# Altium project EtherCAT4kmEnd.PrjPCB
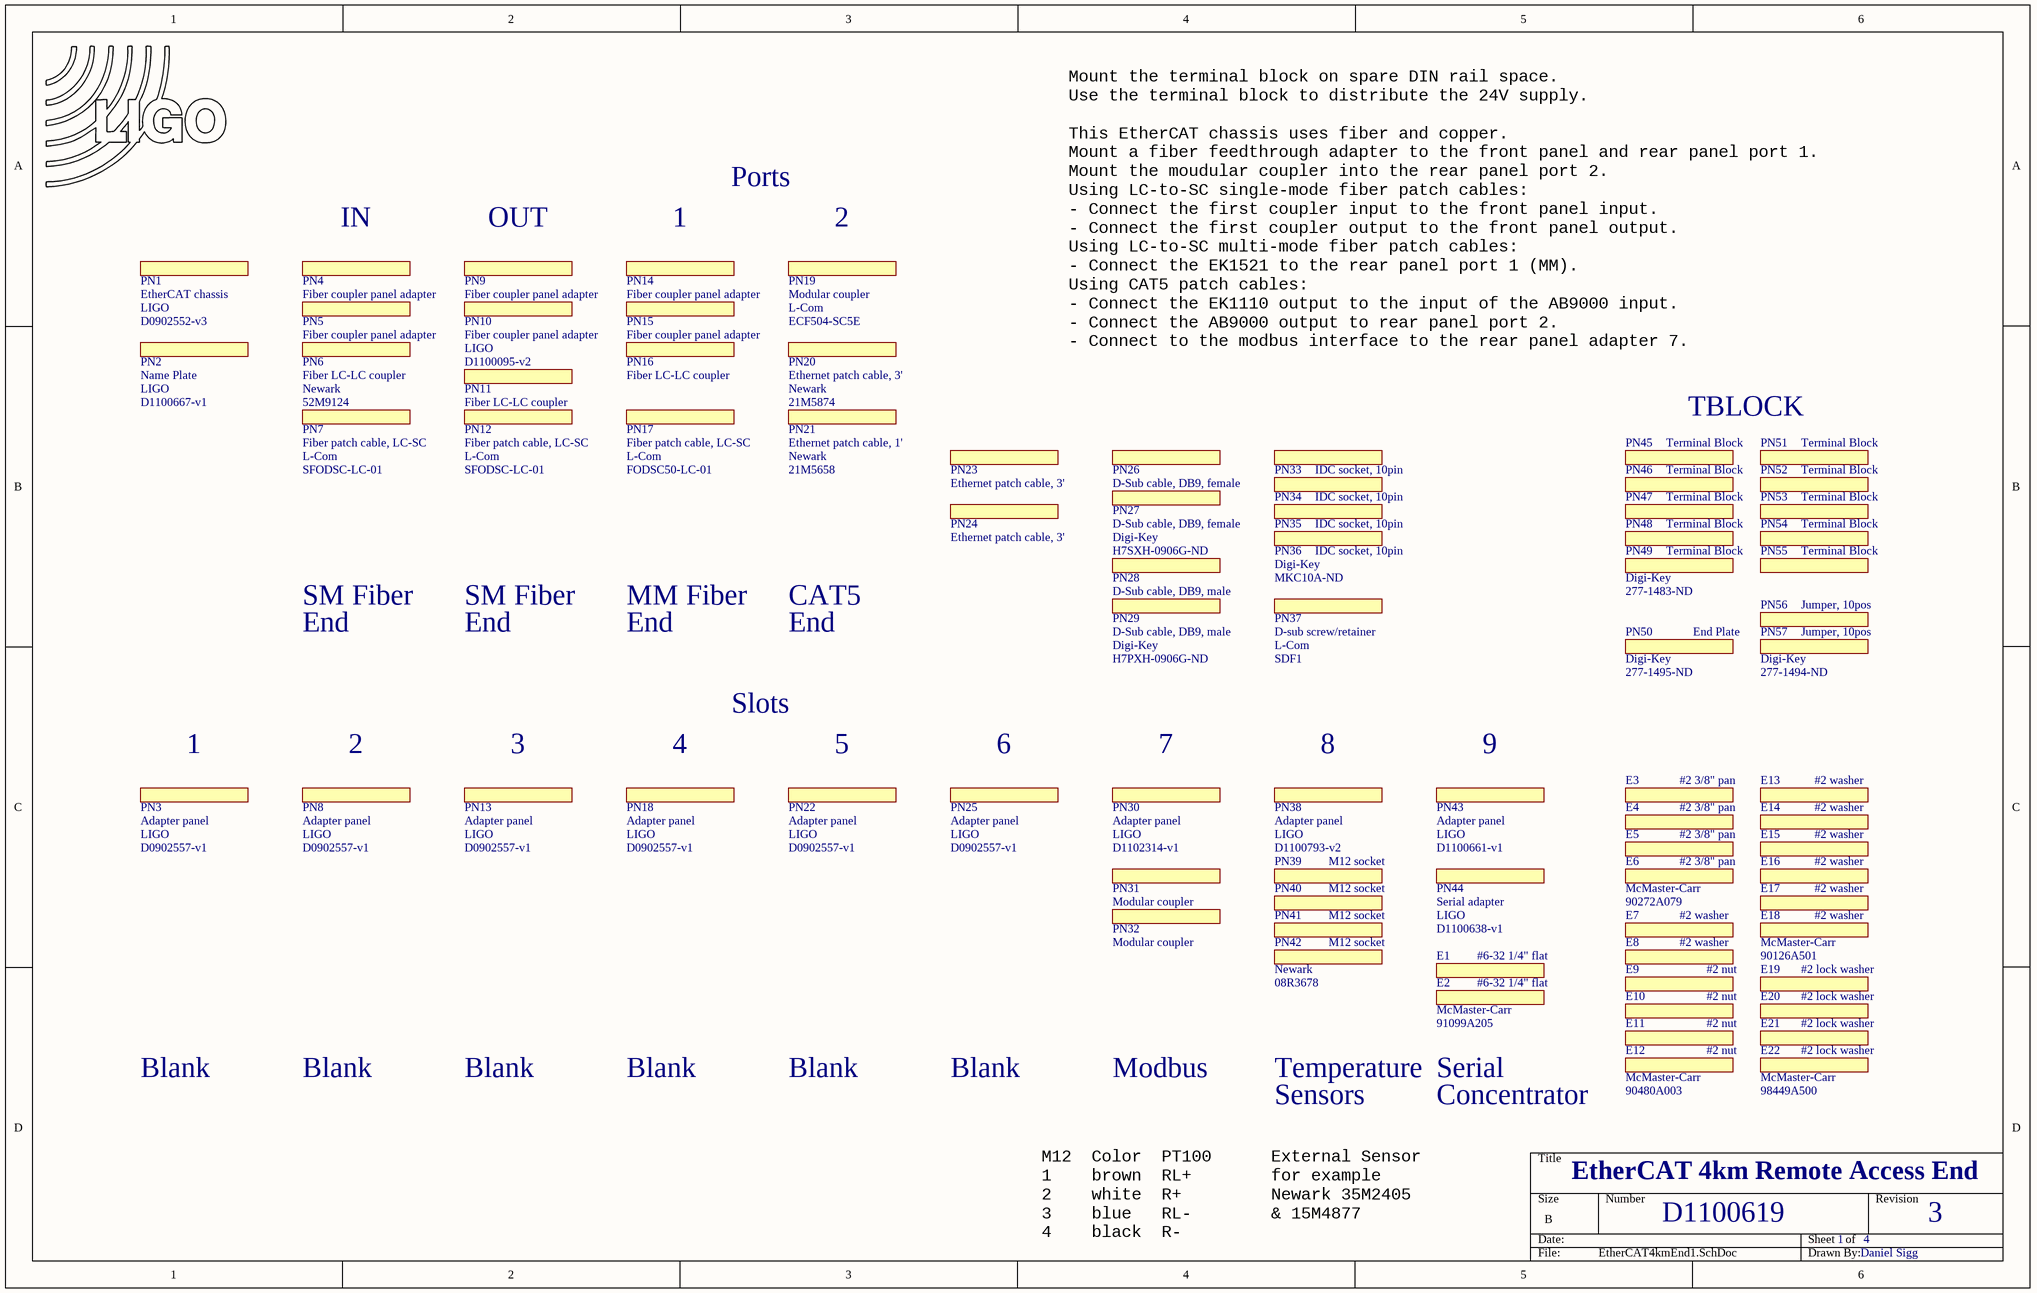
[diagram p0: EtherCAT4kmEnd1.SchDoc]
4 sheets, 87 parts. Net scope: global (net labels, ports and power ports of the same name join across sheets).
Sheets:
  EtherCAT4kmEnd1.SchDoc
  EtherCAT4kmEnd2.SchDoc
  EtherCAT4kmEnd3.SchDoc
  EtherCAT4kmEnd4.SchDoc

## Sheet EtherCAT4kmEnd1.SchDoc: D1100619
size B; Engineer: Daniel Sigg; Revision: 3; PageSetup: Record=PageOptions¦CenterHorizontal=True¦CenterVertical=True¦PrintScale=1.12¦XCorrection=1.00¦YCorrection=1.00¦PrintKind=0¦BorderSize=5000000¦LeftOffset=0¦BottomOffset=0¦Orientation=2¦PaperLength=1000¦PaperWidth=1000¦Scale=100¦PaperSource=7¦PrintQuality=-4¦MediaType=1¦DitherType=10¦PaperKind=11 x 17¦PrintScaleMode=1

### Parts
E1  #6-32 1/4" flat  (mechanical)
E2  #6-32 1/4" flat  Part Number: 91099A205  Distributor: McMaster-Carr  (mechanical)
E3  #2 3/8" pan  (mechanical)
E4  #2 3/8" pan  (mechanical)
E5  #2 3/8" pan  (mechanical)
E6  #2 3/8" pan  Part Number: 90272A079  Distributor: McMaster-Carr  (mechanical)
E7  #2 washer  (mechanical)
E8  #2 washer  (mechanical)
E9  #2 nut  (mechanical)
E10  #2 nut  (mechanical)
E11  #2 nut  (mechanical)
E12  #2 nut  Part Number: 90480A003  Distributor: McMaster-Carr  (mechanical)
E13  #2 washer  (mechanical)
E14  #2 washer  (mechanical)
E15  #2 washer  (mechanical)
E16  #2 washer  (mechanical)
E17  #2 washer  (mechanical)
E18  #2 washer  Part Number: 90126A501  Distributor: McMaster-Carr  (mechanical)
E19  #2 lock washer  (mechanical)
E20  #2 lock washer  (mechanical)
E21  #2 lock washer  (mechanical)
E22  #2 lock washer  Part Number: 98449A500  Distributor: McMaster-Carr  (mechanical)
LOGO?  LIGO logo  [LIGO_LOGO]  (value not drawn)  (graphical)
PN1  EtherCAT chassis  Part Number: D0902552-v3  Distributor: LIGO  (mechanical)
PN2  Name Plate  Part Number: D1100667-v1  Distributor: LIGO  (mechanical)
PN3  Adapter panel  Part Number: D0902557-v1  Distributor: LIGO  (mechanical)
PN4  Fiber coupler panel adapter  (mechanical)
PN5  Fiber coupler panel adapter  (mechanical)
PN6  Fiber LC-LC coupler  Part Number: 52M9124  Distributor: Newark  (mechanical)
PN7  Fiber patch cable, LC-SC  Part Number: SFODSC-LC-01  Distributor: L-Com  (mechanical)
PN8  Adapter panel  Part Number: D0902557-v1  Distributor: LIGO  (mechanical)
PN9  Fiber coupler panel adapter  (mechanical)
PN10  Fiber coupler panel adapter  Part Number: D1100095-v2  Distributor: LIGO  (mechanical)
PN11  Fiber LC-LC coupler  (mechanical)
PN12  Fiber patch cable, LC-SC  Part Number: SFODSC-LC-01  Distributor: L-Com  (mechanical)
PN13  Adapter panel  Part Number: D0902557-v1  Distributor: LIGO  (mechanical)
PN14  Fiber coupler panel adapter  (mechanical)
PN15  Fiber coupler panel adapter  (mechanical)
PN16  Fiber LC-LC coupler  (mechanical)
PN17  Fiber patch cable, LC-SC  Part Number: FODSC50-LC-01  Distributor: L-Com  (mechanical)
PN18  Adapter panel  Part Number: D0902557-v1  Distributor: LIGO  (mechanical)
PN19  Modular coupler  Part Number: ECF504-SC5E  Distributor: L-Com  (mechanical)
PN20  Ethernet patch cable, 3'  Part Number: 21M5874  Distributor: Newark  (mechanical)
PN21  Ethernet patch cable, 1'  Part Number: 21M5658  Distributor: Newark  (mechanical)
PN22  Adapter panel  Part Number: D0902557-v1  Distributor: LIGO  (mechanical)
PN23  Ethernet patch cable, 3'  (mechanical)
PN24  Ethernet patch cable, 3'  (mechanical)
PN25  Adapter panel  Part Number: D0902557-v1  Distributor: LIGO  (mechanical)
PN26  D-Sub cable, DB9, female  (mechanical)
PN27  D-Sub cable, DB9, female  Part Number: H7SXH-0906G-ND  Distributor: Digi-Key  (mechanical)
PN28  D-Sub cable, DB9, male  (mechanical)
PN29  D-Sub cable, DB9, male  Part Number: H7PXH-0906G-ND  Distributor: Digi-Key  (mechanical)
PN30  Adapter panel  Part Number: D1102314-v1  Distributor: LIGO  (mechanical)
PN31  Modular coupler  (mechanical)
PN32  Modular coupler  (mechanical)
PN33  IDC socket, 10pin  (mechanical)
PN34  IDC socket, 10pin  (mechanical)
PN35  IDC socket, 10pin  (mechanical)
PN36  IDC socket, 10pin  Part Number: MKC10A-ND  Distributor: Digi-Key  (mechanical)
PN37  D-sub screw/retainer  Part Number: SDF1  Distributor: L-Com  (mechanical)
PN38  Adapter panel  Part Number: D1100793-v2  Distributor: LIGO  (mechanical)
PN39  M12 socket  (mechanical)
PN40  M12 socket  (mechanical)
PN41  M12 socket  (mechanical)
PN42  M12 socket  Part Number: 08R3678  Distributor: Newark  (mechanical)
PN43  Adapter panel  Part Number: D1100661-v1  Distributor: LIGO  (mechanical)
PN44  Serial adapter  Part Number: D1100638-v1  Distributor: LIGO  (mechanical)
PN45  Terminal Block  (mechanical)
PN46  Terminal Block  (mechanical)
PN47  Terminal Block  (mechanical)
PN48  Terminal Block  (mechanical)
PN49  Terminal Block  Part Number: 277-1483-ND  Distributor: Digi-Key  (mechanical)
PN50  End Plate  Part Number: 277-1495-ND  Distributor: Digi-Key  (mechanical)
PN51  Terminal Block  (mechanical)
PN52  Terminal Block  (mechanical)
PN53  Terminal Block  (mechanical)
PN54  Terminal Block  (mechanical)
PN55  Terminal Block  (mechanical)
PN56  Jumper, 10pos  (mechanical)
PN57  Jumper, 10pos  Part Number: 277-1494-ND  Distributor: Digi-Key  (mechanical)

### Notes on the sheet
- (near PN4) IN
- (near PN9) OUT
- 1
- Ports
- (near PN19) 2
- Mount the terminal block on spare DIN rail space.
  Use the terminal block to distribute the 24V supply.
  This EtherCAT chassis uses fiber and copper.
  Mount a fiber feedthrough adapter to the front panel and rear panel port 1.
  Mount the moudular coupler into the rear panel port 2.
  Using LC-to-SC single-mode fiber patch cables:
  - Connect the first coupler input to the front panel input.
  - Connect the first coupler output to the front panel output.
  Using LC-to-SC multi-mode fiber patch cables:
  - Connect the EK1521 to the rear panel port 1 (MM).
  Using CAT5 patch cables:
  - Connect the EK1110 output to the input of the AB9000 input.
  - Connect the AB9000 output to rear panel port 2.
  - Connect to the modbus interface to the rear panel adapter 7.
- (near PN51) TBLOCK
- SM Fiber
- End
- MM Fiber
- CAT5
- (near PN3) 1
- (near PN8) 2
- (near PN13) 3
- (near PN18) 4
- Slots
- (near PN22) 5
- (near PN25) 6
- (near PN30) 7
- (near PN38) 8
- (near PN43) 9
- Blank
- Modbus
- Temperature
- Sensors
- Serial
- (near E12) Concentrator
- EtherCAT 4km Remote Access End
- M12  Color  PT100
  1    brown  RL+
  2    white  R+
  3    blue   RL-
  4    black  R-
- External Sensor
  for example
  Newark 35M2405
  & 15M4877
- D1100619
- 4
- 3
- Daniel Sigg

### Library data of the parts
E1 = Partlist: #6-32 1/4" flat head screw; Part Number: 91099A205
E2 E6 E12 E18 E22 = Partlist: #6-32 1/4" flat head screw
E3-E5 = Partlist: #6-32 1/4" flat head screw; Part Number: 90272A079
E7 E8 E13-E17 = Partlist: #6-32 1/4" flat head screw; Part Number: 90126A501
E9-E11 = Partlist: #6-32 1/4" flat head screw; Part Number: 90480A003
E19-E21 = Partlist: #6-32 1/4" flat head screw; Part Number: 98449A500
LOGO? = LIGO_logo
PN1 PN2 PN6 PN7 PN10 PN12 PN17 PN19-PN21 PN42 PN44 = Partlist: Additional part number
PN3 PN8 PN13 PN18 PN22 PN25 PN38 = Partlist: Blank
PN4 PN5 PN9 PN14 PN15 = Partlist: Additional part number; Part Number: D1100095-v2
PN11 PN16 = Partlist: Additional part number; Part Number: 52M9124
PN23 PN24 = Partlist: Additional part number; Part Number: 21M5874
PN26 = Partlist: D-Sub cable, DB9, male/open, flat ribbon; Part Number: H7SXH-0906G-ND
PN27 PN29 = Partlist: D-Sub cable, DB9, male/open, flat ribbon
PN28 = Partlist: D-Sub cable, DB9, male/open, flat ribbon; Part Number: H7PXH-0906G-ND
PN30 = Partlist: Modbus adapter, dual
PN31 PN32 = Partlist: Additional part number; Part Number: ECF504-SC5E
PN33-PN35 = Partlist: Part Number: MKC10A-ND
PN36 PN49 PN50 PN57 = Partlist
PN37 = Partlist: D-Sub Hardware Screws and Retainers, Chromate, Pkg/50
PN39-PN41 = Partlist: Additional part number; Part Number: 08R3678
PN43 = Partlist: Serial concentrator
PN45-PN48 PN51-PN55 = Partlist: Part Number: 277-1483-ND
PN56 = Partlist: Part Number: 277-1494-ND

## Sheet EtherCAT4kmEnd2.SchDoc
size B
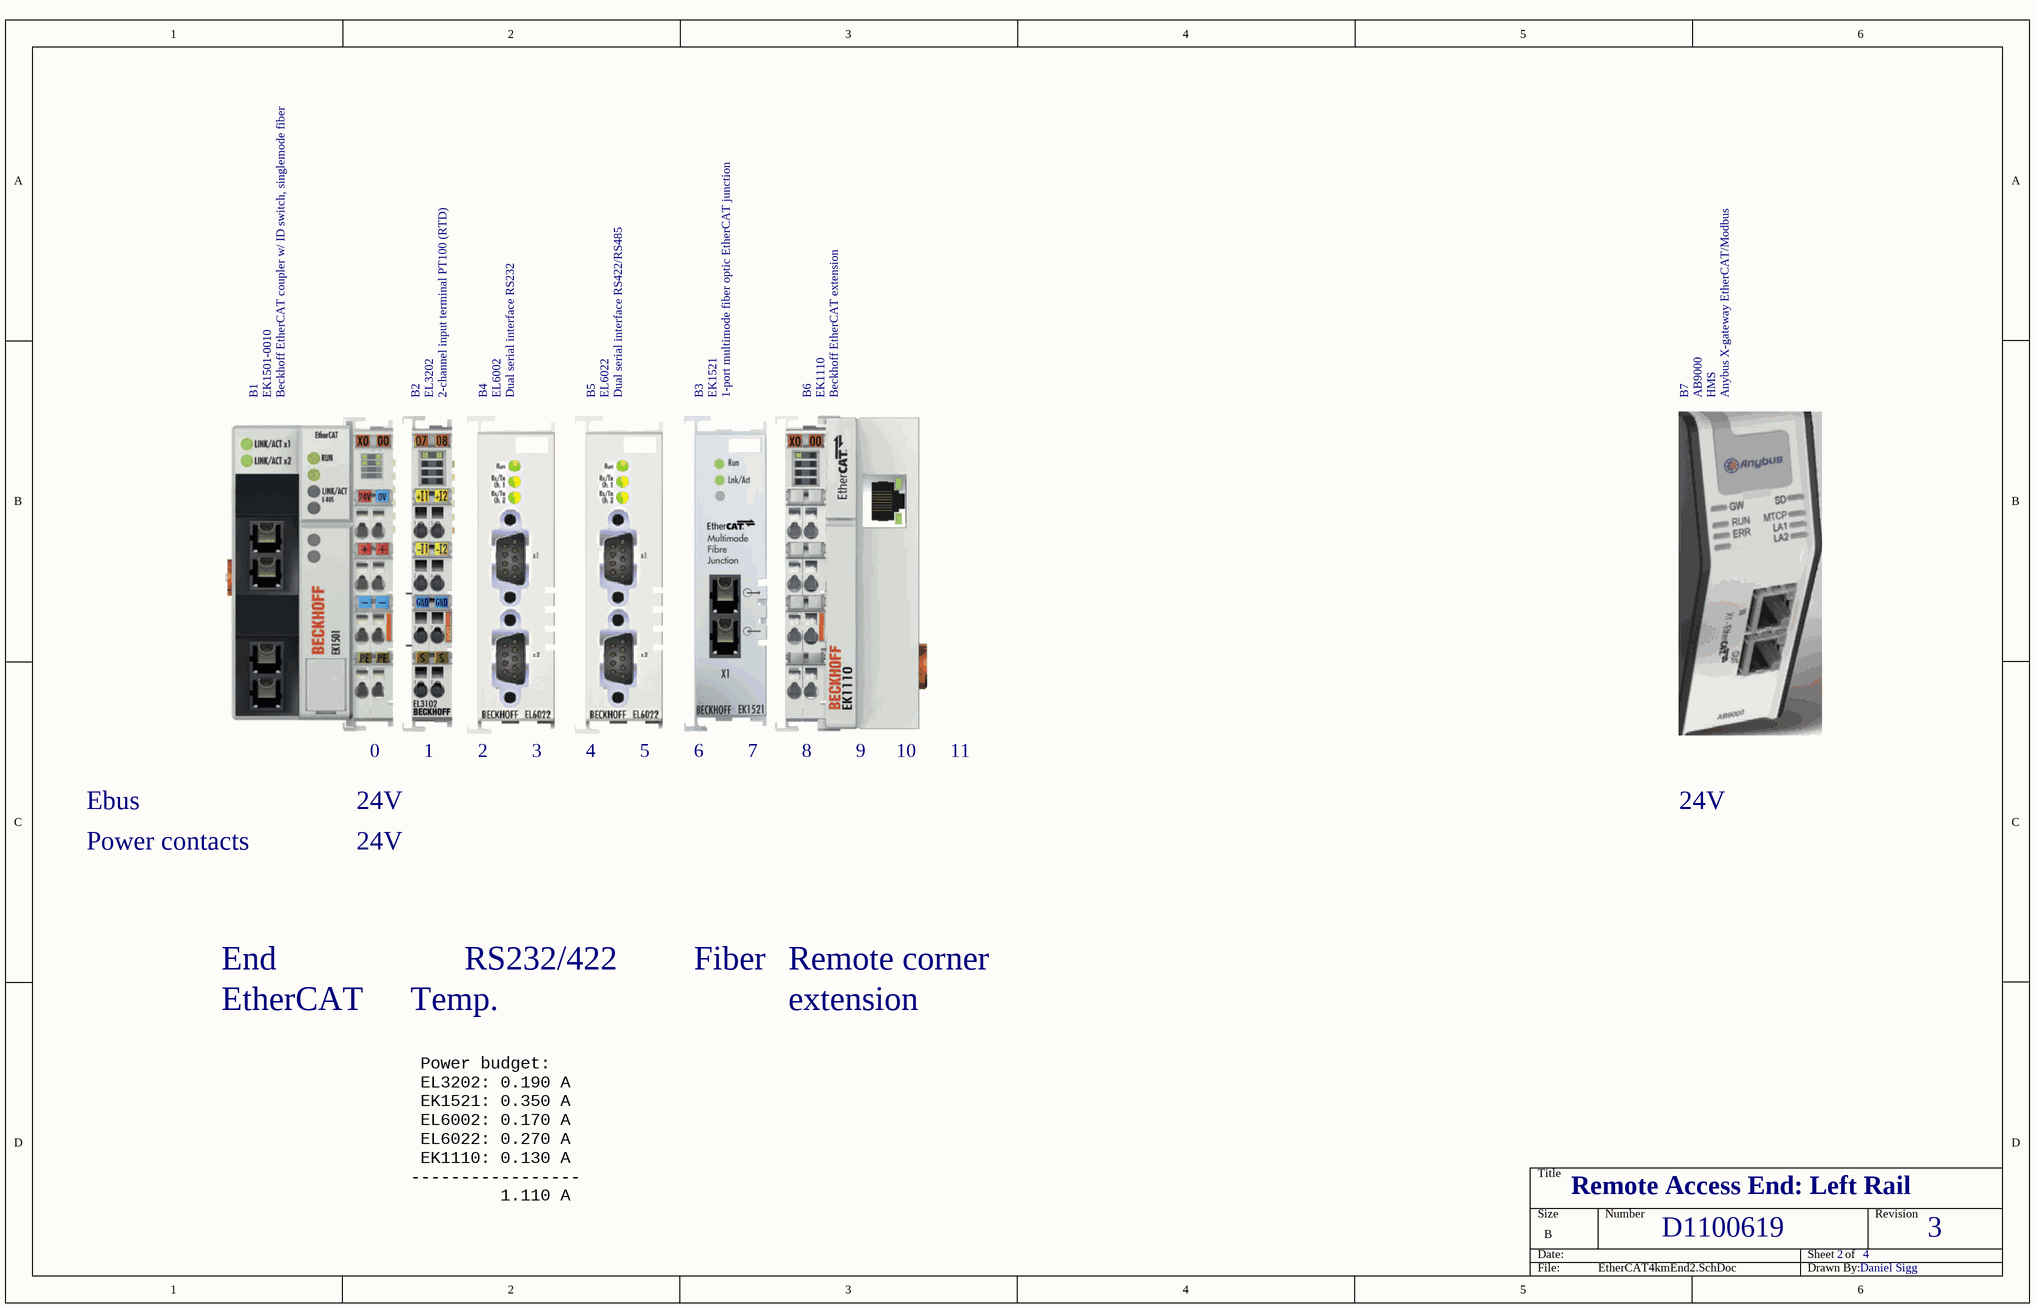
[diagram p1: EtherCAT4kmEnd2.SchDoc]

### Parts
B1  Beckhoff EtherCAT coupler w/ ID switch, singlemode fiber  Part Number: EK1501-0010
B2  2-channel input terminal PT100 (RTD)
B3  1-port multimode fiber optic EtherCAT junction
B4  Dual serial interface RS232
B5  Dual serial interface RS422/RS485
B6  Beckhoff EtherCAT extension
B7  Anybus X-gateway EtherCAT/Modbus  Distributor: HMS

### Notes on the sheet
- (near B2) 0
- 1
- (near B4) 2
- (near B5) 3
- (near B5) 4
- (near B3) 5
- (near B3) 6
- (near B6) 7
- (near B6) 8
- 9
- 10
- 11
- Ebus
- Power contacts
- (near B2) 24V
- 24V
- (near B7) 24V
- End
- RS232/422
- Fiber
- Remote corner
- EtherCAT
- Temp.
- extension
- Remote Access End: Left Rail
- Power budget:
  EL3202: 0.190 A
  EK1521: 0.350 A
  EL6002: 0.170 A
  EL6022: 0.270 A
  EK1110: 0.130 A
  -----------------
  1.110 A
- D1100619
- 2
- 4
- 3
- Daniel Sigg

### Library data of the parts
B1 = EK1501: Beckhoff EtherCAT coupler w/ ID switch, fiber
B2 = EL3202: 2-channel input terminal PT100 (RTD) for 2- or 3-wire connection
B3 = EK1521: Beckhoff 1-port multimode fiber optic EtherCAT junction
B4 = EL6002
B5 = EL6022
B6 = EK1110
B7 = AB9000: HMS Anybus EtherCAT/Modbus

## Sheet EtherCAT4kmEnd3.SchDoc
size B
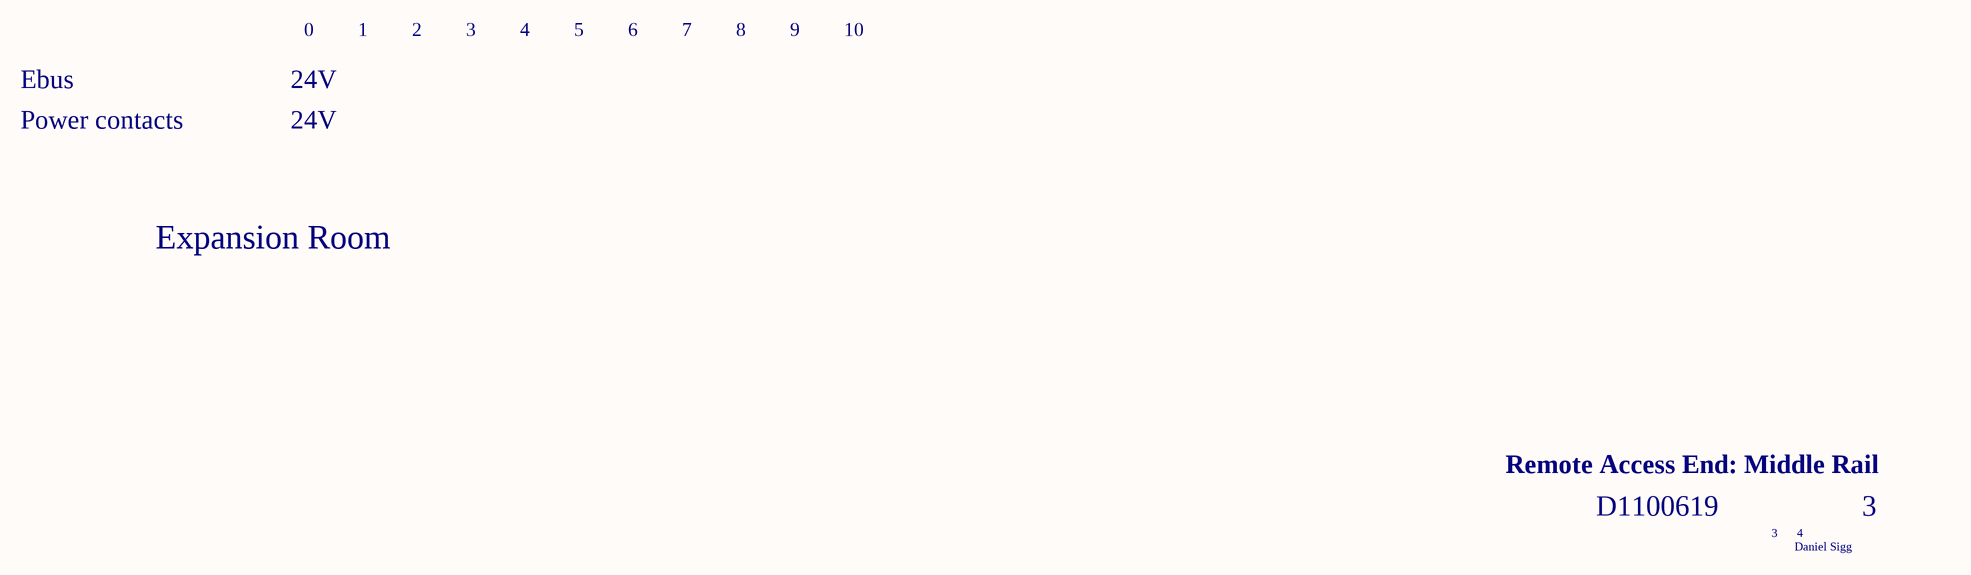
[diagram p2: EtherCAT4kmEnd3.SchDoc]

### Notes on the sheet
- 0
- 1
- 2
- 3
- 4
- 5
- 6
- 7
- 8
- 9
- 10
- Ebus
- Power contacts
- 24V
- Expansion Room
- Remote Access End: Middle Rail
- D1100619
- Daniel Sigg

## Sheet EtherCAT4kmEnd4.SchDoc
size B
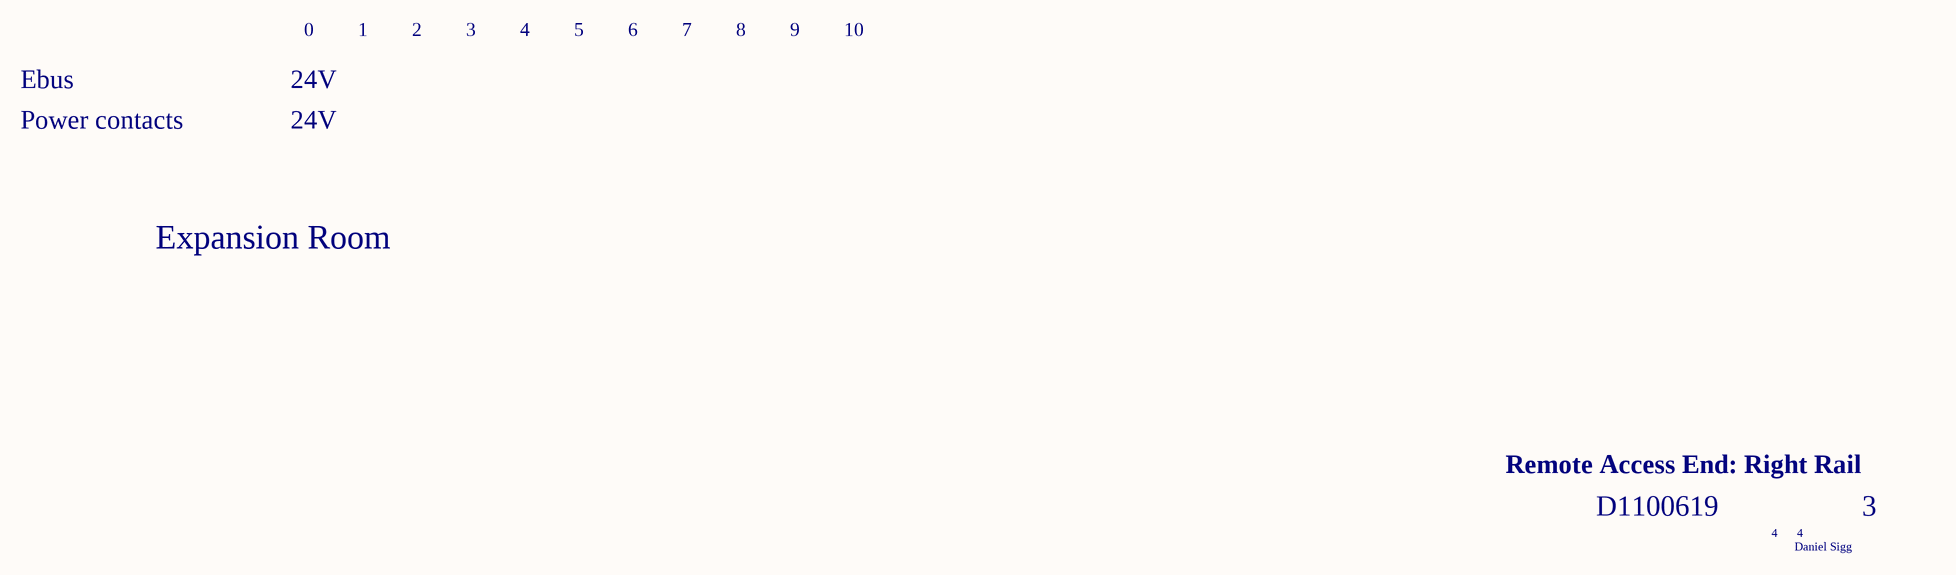
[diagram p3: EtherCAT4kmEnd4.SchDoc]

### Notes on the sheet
- 0
- 1
- 2
- 3
- 4
- 5
- 6
- 7
- 8
- 9
- 10
- Ebus
- Power contacts
- 24V
- Expansion Room
- Remote Access End: Right Rail
- D1100619
- Daniel Sigg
